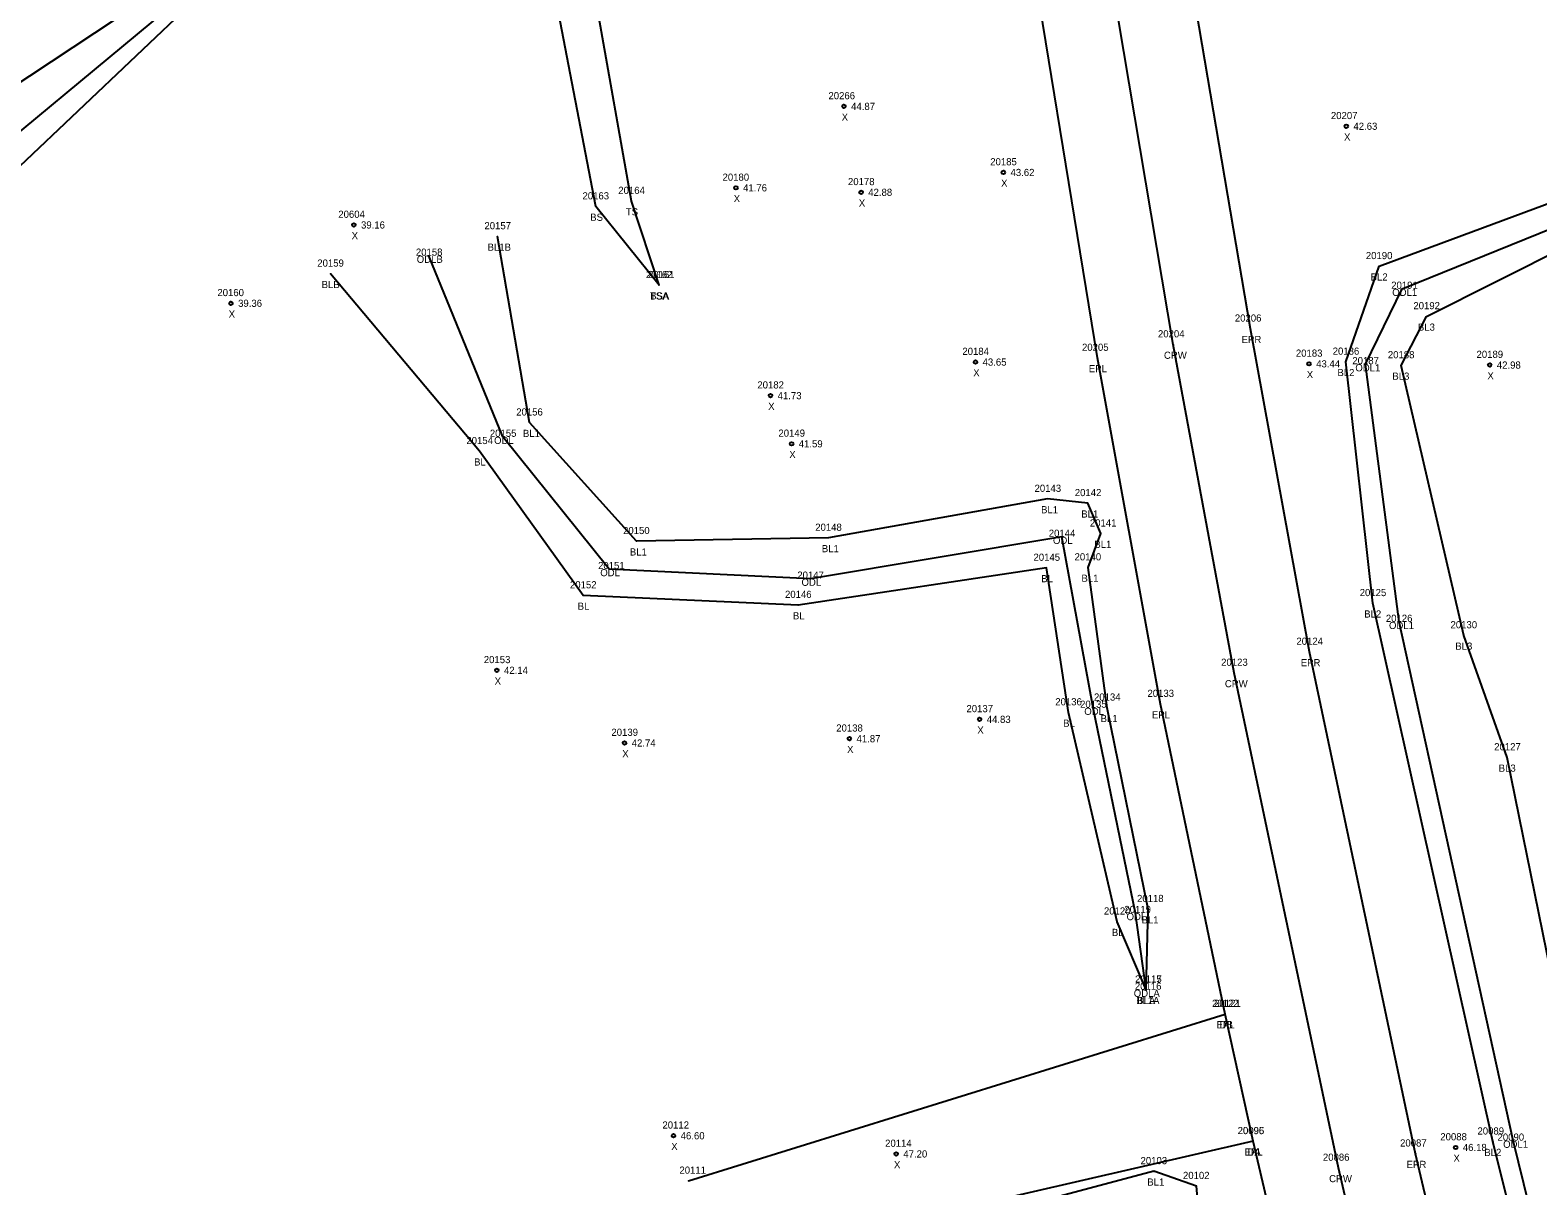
# Model space of a CAD drawing. Extents: x 2445178 to 2446260, y 791158 to 792318.
# Drawn here: x 2445572.9 to 2445783.8, y 791553.6 to 791715.3 of the extents above; entities that cross this region are included whole.
import ezdxf

# ---------------------------------------------------------------- set-up
doc = ezdxf.new("R2010")
doc.units = 0
for name, color, linetype in [('RD_DTM_BkLn1', 7, 'Continuous'), ('RD_DTM_BkLn2', 7, 'Continuous'), ('RD_EX_Driveway', 7, 'Continuous'), ('RD_EX_Driveway_txCode', 7, 'Continuous'), ('RD_EX_H2O', 7, 'Continuous'), ('RD_EX_H2O_txCode', 7, 'Continuous'), ('RD_EX_Road', 7, 'Continuous'), ('RD_EX_Road_txCode', 7, 'Continuous'), ('RD_Sketch8', 7, 'Continuous'), ('RD_SMD_Locator', 7, 'Continuous'), ('RD_SMD_Misc', 7, 'Continuous')]:
    doc.layers.add(name, color=color, linetype=linetype)

msp = doc.modelspace()

# ---------------------------------------------------------------- linework, layer by layer
at = {"layer": 'RD_DTM_BkLn1'}
for points in [[(2445860.1, 791179.04), (2445833.11, 791268.21), (2445816.53, 791324.11), (2445799.46, 791383.44), (2445783.89, 791440.59), (2445769.57, 791497.35), (2445755.95, 791556.11), (2445741.36, 791625.36), (2445732.84, 791671.31), (2445721.28, 791739.8), (2445717.39, 791765.43)], [(2445882.78, 791184.78), (2445856.18, 791275.27), (2445839.04, 791329.43), (2445822.96, 791388.68), (2445805.7, 791444.65), (2445792.52, 791499.62), (2445777.56, 791559.78), (2445760.75, 791635.11), (2445757, 791668.89), (2445761.65, 791682.26), (2445806.3, 791698.85), (2445844.78, 791714.67)], [(2445896.2, 791187.37), (2445865.75, 791277.36), (2445863.45, 791286.42), (2445844.64, 791330.14), (2445831.75, 791389.47), (2445816.24, 791445.72), (2445804.21, 791499.93), (2445790.09, 791561.7), (2445779.57, 791613.54), (2445773.51, 791630.61), (2445764.7, 791668.39), (2445768.27, 791675.25), (2445808.12, 791695.24), (2445844.78, 791714.67)], [(2445729.04, 791581.04), (2445729.31, 791592.31), (2445723.58, 791620.49), (2445720.9, 791640.11), (2445722.71, 791644.85), (2445720.88, 791649.1), (2445715.25, 791649.7), (2445684.57, 791644.25), (2445657.71, 791643.79), (2445642.75, 791660.38), (2445638.27, 791686.44)], [(2445729.04, 791581.04), (2445725, 791590.56), (2445718.18, 791619.83), (2445715.11, 791640.05), (2445680.36, 791634.86), (2445650.24, 791636.2), (2445635.75, 791656.38), (2445614.89, 791681.21)], [(2445839.71, 791171.21), (2445812.99, 791261.63), (2445797.26, 791317.94), (2445780.39, 791374.8), (2445762.73, 791434.98), (2445748.42, 791490.93), (2445737.04, 791541.96), (2445736.07, 791553.56), (2445730.12, 791555.63), (2445697.6, 791546.96), (2445670.73, 791536.08)]]:
    msp.add_lwpolyline(points, dxfattribs=at)
at = {"layer": 'RD_DTM_BkLn2'}
for points in [[(2445660.9, 791679.61), (2445652.02, 791690.62), (2445646.32, 791720.24), (2445644.41, 791741.07), (2445663.02, 791759.06), (2445685.05, 791767.22), (2445701.7, 791773.05)], [(2445660.9, 791679.61), (2445657.03, 791691.38), (2445652.33, 791717.94), (2445651.33, 791738.08), (2445670.27, 791751.65), (2445687.44, 791756.17), (2445702.76, 791764.23)], [(2445612.18, 791734.98), (2445557.56, 791698.84), (2445552.02, 791673.05), (2445513.68, 791664.7), (2445463.32, 791637.22), (2445363.77, 791592.3), (2445292.26, 791558.82)], [(2445612.18, 791734.98), (2445563.15, 791688.49), (2445558.95, 791665.85), (2445520.9, 791652.98), (2445473.7, 791621.85), (2445363.77, 791592.3)]]:
    msp.add_lwpolyline(points, dxfattribs=at)
at = {"layer": 'RD_EX_Driveway'}
for p, q in [((2445664.99, 791554.3), (2445740.09, 791577.64)), ((2445744.01, 791559.83), (2445667.9, 791542.37))]:
    msp.add_line(p, q, dxfattribs=at)
at = {"layer": 'RD_EX_H2O'}
for points in [[(2445748.32, 791780.49), (2445701.12, 791774.43), (2445677.09, 791767.59), (2445662.39, 791761.56), (2445644.36, 791766.93), (2445623.55, 791762.71), (2445618.49, 791746.46), (2445607.67, 791748.78), (2445606.64, 791748.27), (2445612.18, 791734.98), (2445561.56, 791692.97), (2445554.1, 791670.89), (2445517.8, 791656.91), (2445473.7, 791621.85), (2445363.77, 791592.3), (2445292.26, 791558.82)], [(2445885.63, 791185.34), (2445858.54, 791275.66), (2445841.27, 791329.71), (2445824.98, 791389.05), (2445808.2, 791445.07), (2445795.15, 791500.08), (2445780.4, 791559.92), (2445764.43, 791632.51), (2445759.72, 791668.56), (2445764.88, 791679.11), (2445806.8, 791696.09), (2445844.78, 791714.67)], [(2445729.04, 791581.04), (2445727.54, 791591.77), (2445721.62, 791620.49), (2445717.25, 791644.41), (2445682.05, 791638.55), (2445653.89, 791639.89), (2445639.03, 791658.4), (2445628.68, 791683.74)]]:
    msp.add_lwpolyline(points, dxfattribs=at)
at = {"layer": 'RD_EX_Road'}
for points in [[(2445850.42, 791174.36), (2445823.13, 791264.7), (2445806.34, 791321.46), (2445789.41, 791379.89), (2445773.46, 791437.57), (2445759.36, 791494.22), (2445744.01, 791559.83), (2445740.09, 791577.64), (2445731.05, 791621.01), (2445722.21, 791669.43), (2445711, 791738.26), (2445706.49, 791765.2)], [(2445870.82, 791182.02), (2445844.02, 791271.27), (2445827.31, 791326.39), (2445810.32, 791385.52), (2445794.94, 791441.92), (2445780.98, 791497.5), (2445766.72, 791558.1), (2445751.9, 791628.3), (2445743.63, 791673.52), (2445732.07, 791741.61), (2445728.16, 791765.65)]]:
    msp.add_lwpolyline(points, dxfattribs=at)
at = {"layer": 'RD_SMD_Locator'}
for centre, radius in [((2445686.75, 791704.63), 0.25), ((2445757.04, 791701.85), 0.25), ((2445709.06, 791695.39), 0.25), ((2445671.63, 791693.23), 0.25), ((2445689.15, 791692.61), 0.25), ((2445652.02, 791690.62), 0.001), ((2445657.03, 791691.38), 0.001), ((2445618.17, 791688.04), 0.25), ((2445638.27, 791686.44), 0.001), ((2445628.68, 791683.74), 0.001), ((2445761.65, 791682.26), 0.001), ((2445614.89, 791681.21), 0.001), ((2445660.9, 791679.61), 0.001), ((2445660.9, 791679.61), 0.001), ((2445764.88, 791679.11), 0.001), ((2445600.97, 791677.08), 0.25), ((2445768.27, 791675.25), 0.001), ((2445743.63, 791673.52), 0.001), ((2445722.21, 791669.43), 0.001), ((2445732.84, 791671.31), 0.001), ((2445705.15, 791668.86), 0.25), ((2445751.83, 791668.61), 0.25), ((2445757, 791668.89), 0.001), ((2445759.72, 791668.56), 0.001), ((2445764.7, 791668.39), 0.001), ((2445777.11, 791668.44), 0.25), ((2445676.47, 791664.16), 0.25), ((2445642.75, 791660.38), 0.001), ((2445639.03, 791658.4), 0.001), ((2445679.42, 791657.42), 0.25), ((2445635.75, 791656.38), 0.001), ((2445715.25, 791649.7), 0.001), ((2445720.88, 791649.1), 0.001), ((2445684.57, 791644.25), 0.001), ((2445717.25, 791644.41), 0.001), ((2445722.71, 791644.85), 0.001), ((2445657.71, 791643.79), 0.001), ((2445653.89, 791639.89), 0.001), ((2445715.11, 791640.05), 0.001), ((2445720.9, 791640.11), 0.001), ((2445682.05, 791638.55), 0.001), ((2445650.24, 791636.2), 0.001), ((2445680.36, 791634.86), 0.001), ((2445760.75, 791635.11), 0.001), ((2445764.43, 791632.51), 0.001), ((2445773.51, 791630.61), 0.001), ((2445751.9, 791628.3), 0.001), ((2445638.18, 791625.73), 0.25), ((2445741.36, 791625.36), 0.001), ((2445731.05, 791621.01), 0.001), ((2445705.73, 791618.87), 0.25), ((2445718.18, 791619.83), 0.001), ((2445721.62, 791620.49), 0.001), ((2445723.58, 791620.49), 0.001), ((2445656.05, 791615.56), 0.25), ((2445687.51, 791616.16), 0.25), ((2445779.57, 791613.54), 0.001), ((2445727.54, 791591.77), 0.001), ((2445729.31, 791592.31), 0.001), ((2445725, 791590.56), 0.001), ((2445729.04, 791581.04), 0.001), ((2445729.04, 791581.04), 0.001), ((2445729.04, 791581.04), 0.001), ((2445740.09, 791577.64), 0.001), ((2445740.09, 791577.64), 0.001), ((2445662.9, 791560.61), 0.25), ((2445744.01, 791559.83), 0.001), ((2445744.01, 791559.83), 0.001), ((2445777.56, 791559.78), 0.001), ((2445780.4, 791559.92), 0.001), ((2445694.06, 791558.06), 0.25), ((2445766.72, 791558.1), 0.001), ((2445772.35, 791558.97), 0.25), ((2445730.12, 791555.63), 0.001), ((2445755.95, 791556.11), 0.001), ((2445664.99, 791554.3), 0.001)]:
    msp.add_circle(centre, radius, dxfattribs=at)

# ---------------------------------------------------------------- texts
at = {"layer": 'RD_EX_Driveway_txCode'}
for s, p in [('20122', (2445738.26, 791578.64)), ('DB', (2445739.32, 791575.64)), ('20096', (2445741.83, 791560.83)), ('DA', (2445743.22, 791557.83)), ('20111', (2445663.73, 791555.3))]:
    msp.add_text(s, height=1, dxfattribs=at).set_placement(p)
at = {"layer": 'RD_EX_H2O_txCode'}
for s, p in [('20158', (2445626.85, 791683.74)), ('ODLB', (2445626.97, 791682.74)), ('20191', (2445763.33, 791679.11)), ('ODL1', (2445763.47, 791678.11)), ('20187', (2445757.89, 791668.56)), ('ODL1', (2445758.31, 791667.56)), ('20155', (2445637.2, 791658.4)), ('ODL', (2445637.79, 791657.4)), ('20144', (2445715.41, 791644.41)), ('ODL', (2445716, 791643.41)), ('20151', (2445652.34, 791639.89)), ('ODL', (2445652.65, 791638.89)), ('20147', (2445680.22, 791638.55)), ('ODL', (2445680.81, 791637.55)), ('20126', (2445762.58, 791632.51)), ('ODL1', (2445763.02, 791631.51)), ('20135', (2445719.79, 791620.49)), ('ODL', (2445720.38, 791619.49)), ('20119', (2445725.99, 791591.77)), ('ODL', (2445726.3, 791590.77)), ('ODLA', (2445727.3, 791580.04)), ('20116', (2445727.46, 791581.04)), ('20090', (2445778.21, 791559.92)), ('ODL1', (2445778.99, 791558.92))]:
    msp.add_text(s, height=1, dxfattribs=at).set_placement(p)
at = {"layer": 'RD_EX_Road_txCode'}
for s, p in [('20206', (2445741.45, 791674.52)), ('EPR', (2445742.4, 791671.52)), ('20205', (2445720.06, 791670.43)), ('EPL', (2445721.01, 791667.43)), ('20124', (2445750.06, 791629.3)), ('EPR', (2445750.67, 791626.3)), ('20133', (2445729.22, 791622.01)), ('EPL', (2445729.85, 791619.01)), ('20121', (2445738.54, 791578.64)), ('EPL', (2445738.89, 791575.64)), ('20095', (2445741.85, 791560.83)), ('20087', (2445764.57, 791559.1)), ('EPL', (2445742.81, 791557.83)), ('EPR', (2445765.49, 791556.1))]:
    msp.add_text(s, height=1, dxfattribs=at).set_placement(p)
at = {"layer": 'RD_Sketch8'}
for s, p in [('20266', (2445684.58, 791705.63)), ('X', (2445686.43, 791702.63)), ('44.87', (2445687.75, 791704.13)), ('20207', (2445754.89, 791702.85)), ('42.63', (2445758.04, 791701.35)), ('X', (2445756.73, 791699.85)), ('20185', (2445707.22, 791696.39)), ('20180', (2445669.76, 791694.23)), ('43.62', (2445710.06, 791694.89)), ('41.76', (2445672.63, 791692.73)), ('20178', (2445687.31, 791693.61)), ('42.88', (2445690.15, 791692.11)), ('X', (2445708.74, 791693.39)), ('X', (2445671.32, 791691.23)), ('X', (2445688.83, 791690.61)), ('20604', (2445615.99, 791689.04)), ('39.16', (2445619.17, 791687.54)), ('X', (2445617.86, 791686.04)), ('20160', (2445599.07, 791678.08)), ('X', (2445600.65, 791675.08)), ('39.36', (2445601.97, 791676.58)), ('20184', (2445703.32, 791669.86)), ('43.65', (2445706.15, 791668.36)), ('20183', (2445749.99, 791669.61)), ('20189', (2445775.27, 791669.44)), ('X', (2445704.84, 791666.86)), ('X', (2445751.51, 791666.61)), ('43.44', (2445752.83, 791668.11)), ('X', (2445776.79, 791666.44)), ('42.98', (2445778.11, 791667.94)), ('20182', (2445674.63, 791665.16)), ('X', (2445676.15, 791662.16)), ('41.73', (2445677.47, 791663.66)), ('20149', (2445677.58, 791658.42)), ('41.59', (2445680.42, 791656.92)), ('X', (2445679.1, 791655.42)), ('20153', (2445636.35, 791626.73)), ('42.14', (2445639.18, 791625.23)), ('X', (2445637.87, 791623.73)), ('20137', (2445703.89, 791619.87)), ('44.83', (2445706.73, 791618.37)), ('20139', (2445654.21, 791616.56)), ('20138', (2445685.67, 791617.16)), ('41.87', (2445688.51, 791615.66)), ('X', (2445705.41, 791616.87)), ('X', (2445655.73, 791613.56)), ('42.74', (2445657.05, 791615.06)), ('X', (2445687.19, 791614.16)), ('20112', (2445661.35, 791561.61)), ('46.60', (2445663.9, 791560.11)), ('20114', (2445692.51, 791559.06)), ('20088', (2445770.2, 791559.97)), ('X', (2445662.58, 791558.61)), ('47.20', (2445695.06, 791557.56)), ('X', (2445772.04, 791556.97)), ('46.18', (2445773.35, 791558.47)), ('X', (2445693.75, 791556.06))]:
    msp.add_text(s, height=1, dxfattribs=at).set_placement(p)
at = {"layer": 'RD_SMD_Misc'}
for s, p in [('20163', (2445650.16, 791691.62)), ('20164', (2445655.17, 791692.38)), ('20157', (2445636.44, 791687.44)), ('BS', (2445651.24, 791688.62)), ('TS', (2445656.23, 791689.38)), ('BL1B', (2445636.88, 791684.44)), ('20190', (2445759.78, 791683.26)), ('20159', (2445613.05, 791682.21)), ('BLB', (2445613.66, 791679.21)), ('20162', (2445659.04, 791680.61)), ('20161', (2445659.32, 791680.61)), ('BL2', (2445760.45, 791680.26)), ('TSA', (2445659.61, 791677.61)), ('BSA', (2445659.63, 791677.61)), ('20192', (2445766.43, 791676.25)), ('BL3', (2445767.06, 791673.25)), ('20204', (2445730.69, 791672.31)), ('CRW', (2445731.53, 791669.31)), ('20186', (2445755.14, 791669.89)), ('20188', (2445762.86, 791669.39)), ('BL2', (2445755.8, 791666.89)), ('BL3', (2445763.49, 791666.39)), ('20156', (2445640.89, 791661.38)), ('BL1', (2445641.83, 791658.38)), ('20154', (2445633.91, 791657.38)), ('BL', (2445634.99, 791654.38)), ('20143', (2445713.42, 791650.7)), ('20142', (2445719.05, 791650.1)), ('BL1', (2445714.33, 791647.7)), ('20148', (2445682.73, 791645.25)), ('BL1', (2445719.96, 791647.1)), ('20141', (2445721.16, 791645.85)), ('20150', (2445655.84, 791644.79)), ('BL1', (2445656.79, 791641.79)), ('BL1', (2445683.65, 791642.25)), ('20145', (2445713.27, 791641.05)), ('20140', (2445719.02, 791641.11)), ('BL1', (2445721.79, 791642.85)), ('20152', (2445648.41, 791637.2)), ('BL', (2445714.35, 791638.05)), ('BL1', (2445719.98, 791638.11)), ('20146', (2445678.5, 791635.86)), ('20125', (2445758.92, 791636.11)), ('BL', (2445649.49, 791634.2)), ('BL', (2445679.61, 791632.86)), ('BL2', (2445759.55, 791633.11)), ('20130', (2445771.63, 791631.61)), ('BL3', (2445772.3, 791628.61)), ('20123', (2445739.53, 791626.36)), ('CRW', (2445740.05, 791623.36)), ('20136', (2445716.32, 791620.83)), ('20134', (2445721.74, 791621.49)), ('BL', (2445717.42, 791617.83)), ('BL1', (2445722.66, 791618.49)), ('20127', (2445777.74, 791614.54)), ('BL3', (2445778.37, 791611.54)), ('20118', (2445727.76, 791593.31)), ('20120', (2445723.13, 791591.56)), ('BL1', (2445728.39, 791590.31)), ('BL', (2445724.24, 791588.56)), ('20115', (2445727.49, 791582.04)), ('20117', (2445727.49, 791582.04)), ('BL1A', (2445727.63, 791579.04)), ('BLA', (2445727.79, 791579.04)), ('20089', (2445775.4, 791560.78)), ('20103', (2445728.25, 791556.63)), ('20086', (2445753.77, 791557.11)), ('BL2', (2445776.36, 791557.78)), ('20102', (2445734.19, 791554.56)), ('BL1', (2445729.2, 791553.63)), ('CRW', (2445754.64, 791554.11))]:
    msp.add_text(s, height=1, dxfattribs=at).set_placement(p)

doc.saveas('drawing.dxf')
